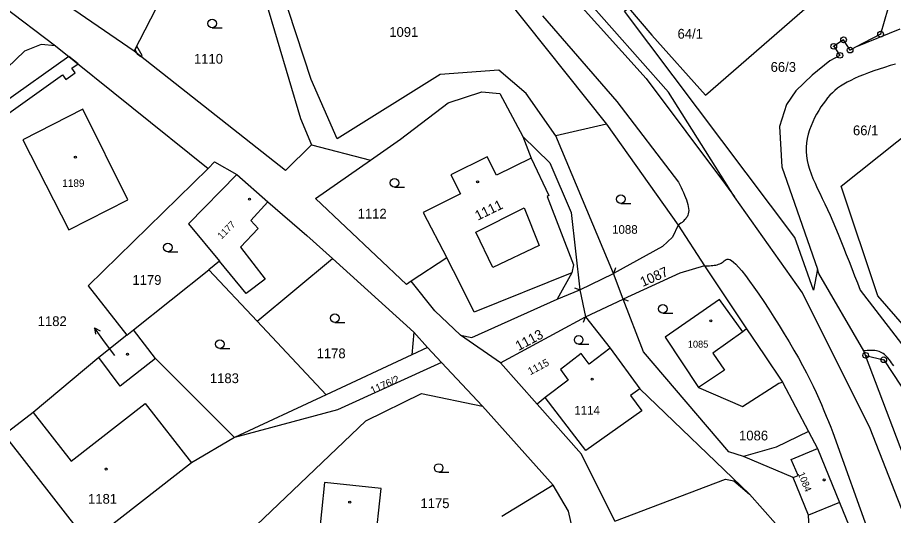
# Model space of a CAD drawing. Extents: x -504988 to -494607, y -1123820 to -1114018.
# Drawn here: x -497712.4 to -497559.8, y -1119487.8 to -1119400.9 of the extents above; entities that cross this region are included whole.
import ezdxf

# ---------------------------------------------------------------- set-up
doc = ezdxf.new("R2010")
doc.units = 0
for name, color, linetype in [('Hranice parcel', 7, 'Continuous'), ('Parcelní čísla', 7, 'Continuous'), ('Pop  PČ popisy', 7, 'Continuous'), ('Vnitřní kresba', 7, 'Continuous'), ('Věcná břemena k části', 7, 'Continuous'), ('Značky bodu BP', 7, 'Continuous'), ('Značky budov', 7, 'Continuous'), ('Značky kultur', 7, 'Continuous')]:
    doc.layers.add(name, color=color, linetype=linetype)

msp = doc.modelspace()

# ---------------------------------------------------------------- linework, layer by layer
at = {"layer": 'Hranice parcel'}
for p, q in [((-497640.86, -1119380.47), (-497609.75, -1119419.53)), ((-497692.07, -1119406.83), (-497682.53, -1119388.18)), ((-497692.07, -1119406.83), (-497711.51, -1119393.46)), ((-497715.1, -1119398.79), (-497705.77, -1119405.86)), ((-497705.77, -1119405.86), (-497679.17, -1119427.27)), ((-497609.75, -1119419.53), (-497618.56, -1119421.58)), ((-497609.75, -1119419.53), (-497597.28, -1119437.17)), ((-497608.52, -1119445.56), (-497618.56, -1119421.58)), ((-497661.14, -1119423.16), (-497650.9, -1119425.81)), ((-497597.28, -1119437.17), (-497592.68, -1119444.27)), ((-497670.65, -1119453.9), (-497657.53, -1119442.97)), ((-497692.2, -1119455.41), (-497679.07, -1119444.93)), ((-497679.07, -1119444.93), (-497670.65, -1119453.9)), ((-497606.86, -1119450.08), (-497608.52, -1119445.56)), ((-497592.68, -1119444.27), (-497585.34, -1119455.21)), ((-497614.4, -1119448.4), (-497613.4, -1119453.14)), ((-497628.22, -1119461.15), (-497613.4, -1119453.14)), ((-497613.4, -1119453.14), (-497609.12, -1119458.59)), ((-497670.65, -1119453.9), (-497658.59, -1119466.73)), ((-497693.35, -1119456.35), (-497692.2, -1119455.41)), ((-497688.32, -1119460.41), (-497692.2, -1119455.41)), ((-497628.22, -1119461.15), (-497635.18, -1119456.31)), ((-497693.35, -1119456.35), (-497698.21, -1119460.22)), ((-497638.51, -1119461.11), (-497640.96, -1119458.51)), ((-497564.6, -1119459.85), (-497564.89, -1119459.08)), ((-497674.56, -1119474.16), (-497688.32, -1119460.41)), ((-497550.62, -1119497.04), (-497564.6, -1119459.85)), ((-497631.38, -1119468.7), (-497638.51, -1119461.11)), ((-497621.82, -1119468.39), (-497628.22, -1119461.15)), ((-497579.08, -1119464.53), (-497574.57, -1119473.11)), ((-497658.59, -1119466.73), (-497674.56, -1119474.16)), ((-497631.38, -1119468.7), (-497619.07, -1119482.47)), ((-497714.71, -1119473.71), (-497700, -1119492.59)), ((-497619.07, -1119482.47), (-497627.97, -1119487.92))]:
    msp.add_line(p, q, dxfattribs=at)
for points in [[(-497682.53, -1119388.18), (-497678.13, -1119389.24), (-497673.06, -1119392.46), (-497669.18, -1119397.97), (-497663.1, -1119418.57), (-497661.14, -1119423.16)], [(-497618.56, -1119421.58), (-497623.74, -1119414.22), (-497628.54, -1119410.1), (-497638.72, -1119410.91), (-497656.7, -1119422.11), (-497661.2, -1119411.73), (-497667.82, -1119391.52)], [(-497605.92, -1119399.25), (-497601.85, -1119404.03), (-497592.53, -1119414.5), (-497565.47, -1119390.86)], [(-497565.47, -1119390.86), (-497560.73, -1119399.46), (-497561.99, -1119403.85), (-497566.37, -1119406.14), (-497567.32, -1119406.63), (-497568.45, -1119404.84), (-497570.16, -1119405.97), (-497569.1, -1119407.54), (-497570.84, -1119408.48), (-497573.91, -1119410.97), (-497576.78, -1119413.73), (-497578.4, -1119416.13), (-497579.64, -1119419.92), (-497579.2, -1119426.96), (-497573.02, -1119444.83)], [(-497534.22, -1119818.76), (-497527.7, -1119797.51), (-497526.57, -1119794.64), (-497519.56, -1119770.79), (-497516.99, -1119756.52), (-497516.74, -1119750.54), (-497517.29, -1119646.04), (-497517.49, -1119635.34), (-497517.68, -1119614.14), (-497518.78, -1119606.17), (-497521.17, -1119596.67), (-497524.36, -1119587.14), (-497528.66, -1119575.06), (-497536.08, -1119553.14), (-497545.22, -1119526.23), (-497548.05, -1119512.85), (-497563.82, -1119472.59), (-497575.6, -1119448.97), (-497587.45, -1119432.22), (-497598.97, -1119413.96), (-497613.75, -1119397.19), (-497616.09, -1119394)], [(-497573.02, -1119444.83), (-497573.67, -1119448.5), (-497576.94, -1119439.33), (-497606.6, -1119399.85), (-497605.92, -1119399.25)], [(-497705.77, -1119405.86), (-497708.27, -1119405.63), (-497711.19, -1119406.83), (-497760.1, -1119453.82), (-497752.95, -1119458.24), (-497750.43, -1119465.73)], [(-497661.14, -1119423.16), (-497665.72, -1119427.6), (-497692.07, -1119406.83)], [(-497650.9, -1119425.81), (-497645.65, -1119422.13), (-497637.35, -1119415.83), (-497631.5, -1119413.89), (-497628.34, -1119414.17), (-497624.36, -1119421.69)], [(-497552.64, -1119460.76), (-497562.49, -1119449.45), (-497568.85, -1119430.36), (-497549.48, -1119414.92)], [(-497693.16, -1119432.73), (-497701.01, -1119416.95), (-497711.46, -1119422.26), (-497703.47, -1119437.95), (-497693.16, -1119432.73)], [(-497624.36, -1119421.69), (-497622.89, -1119425.48), (-497628.93, -1119428.44), (-497630.55, -1119425.22), (-497636.86, -1119428.4), (-497635.21, -1119431.69), (-497641.72, -1119434.94), (-497637.61, -1119442.83), (-497643.77, -1119446.92)], [(-497624.36, -1119421.69), (-497619.61, -1119426.29), (-497615.91, -1119434.92), (-497614.4, -1119448.4)], [(-497643.77, -1119446.92), (-497644.6, -1119447.47), (-497660.47, -1119432.53), (-497650.9, -1119425.81)], [(-497679.17, -1119427.27), (-497700.07, -1119447.75), (-497693.35, -1119456.35)], [(-497679.17, -1119427.27), (-497678.07, -1119426.12), (-497674.15, -1119428.32)], [(-497674.15, -1119428.32), (-497682.61, -1119436.91), (-497677.19, -1119443.44), (-497679.07, -1119444.93)], [(-497674.15, -1119428.32), (-497668.75, -1119433.1), (-497661.96, -1119438.95), (-497657.53, -1119442.97)], [(-497597.28, -1119437.17), (-497598.23, -1119439.27), (-497600.01, -1119440.86), (-497608.52, -1119445.56)], [(-497657.53, -1119442.97), (-497643.34, -1119455.83), (-497640.96, -1119458.51)], [(-497592.68, -1119444.27), (-497596.99, -1119445.5), (-497606.86, -1119450.08)], [(-497564.89, -1119459.08), (-497572.75, -1119445.6), (-497573.02, -1119444.83)], [(-497635.18, -1119456.31), (-497639.67, -1119452.11), (-497643.77, -1119446.92)], [(-497635.18, -1119456.31), (-497633.25, -1119456.73), (-497618.35, -1119450.04), (-497614.4, -1119448.4)], [(-497585.9, -1119477.5), (-497588.42, -1119476.65), (-497603.33, -1119459.22), (-497606.86, -1119450.08)], [(-497585.34, -1119455.21), (-497586.01, -1119455.76), (-497590.07, -1119450.09), (-497599.56, -1119456.68), (-497593.72, -1119465.46), (-497586.09, -1119468.78), (-497579.72, -1119464.7), (-497579.08, -1119464.53)], [(-497585.34, -1119455.21), (-497582.3, -1119459.75), (-497579.08, -1119464.53)], [(-497640.96, -1119458.51), (-497643.66, -1119459.77), (-497658.59, -1119466.73)], [(-497609.12, -1119458.59), (-497612.76, -1119461.36), (-497614.15, -1119459.53), (-497617.8, -1119462.34), (-497616.43, -1119464.15), (-497620.43, -1119467.2), (-497621.82, -1119468.39)], [(-497609.12, -1119458.59), (-497603.95, -1119465.69), (-497584.82, -1119484.08)], [(-497698.21, -1119460.22), (-497709.69, -1119469.8), (-497714.71, -1119473.71)], [(-497688.32, -1119460.41), (-497694.5, -1119465.25), (-497698.21, -1119460.22)], [(-497564.6, -1119459.85), (-497561.45, -1119460.61), (-497553.96, -1119472.01), (-497537.91, -1119494.15)], [(-497638.51, -1119461.11), (-497656.63, -1119469.34), (-497674.56, -1119474.16)], [(-497670.72, -1119489.47), (-497651.69, -1119471.25), (-497642.02, -1119466.49), (-497631.38, -1119468.7)], [(-497608.32, -1119488.74), (-497614.14, -1119477.09), (-497621.82, -1119468.39)], [(-497574.57, -1119473.11), (-497580.2, -1119475.88), (-497585.9, -1119477.5)], [(-497574.57, -1119473.11), (-497572.99, -1119476.08), (-497569.18, -1119485.53), (-497566.97, -1119490.89)], [(-497674.56, -1119474.16), (-497682.06, -1119478.61), (-497700, -1119492.59)], [(-497574.28, -1119493.19), (-497574.58, -1119487.69), (-497577.21, -1119481.15), (-497585.9, -1119477.5)], [(-497655.54, -1119502.25), (-497650.53, -1119499.37), (-497650.13, -1119493.31), (-497649.04, -1119483.09), (-497658.87, -1119482.04), (-497659.96, -1119492.25), (-497658.33, -1119497.4), (-497655.54, -1119502.25)], [(-497608.32, -1119488.74), (-497589, -1119481.44), (-497587.57, -1119481.74), (-497584.82, -1119484.08)], [(-497608.1, -1119523.83), (-497616.4, -1119487.03), (-497619.07, -1119482.47)], [(-497584.82, -1119484.08), (-497580.33, -1119489.19), (-497578.59, -1119497.9), (-497580.72, -1119500.24)]]:
    msp.add_lwpolyline(points, dxfattribs=at)
at = {"layer": 'Pop  PČ popisy'}
for p, q in [((-497697.21, -1119457.47), (-497698.97, -1119455.04)), ((-497698.97, -1119455.04), (-497697.98, -1119455.56)), ((-497698.97, -1119455.04), (-497698.79, -1119456.15)), ((-497695.45, -1119459.9), (-497697.21, -1119457.47))]:
    msp.add_line(p, q, dxfattribs=at)
at = {"layer": 'Vnitřní kresba'}
for p, q in [((-497615.86, -1119397.09), (-497602.87, -1119411.56)), ((-497620.89, -1119400.65), (-497607.94, -1119415.57)), ((-497558.65, -1119403), (-497566.37, -1119406.14)), ((-497602.87, -1119411.56), (-497589.05, -1119430.07)), ((-497607.94, -1119415.57), (-497597.22, -1119429.65)), ((-497622.89, -1119425.48), (-497619.81, -1119431.99)), ((-497589.05, -1119430.07), (-497587.45, -1119432.22)), ((-497668.75, -1119433.1), (-497671.71, -1119436.35)), ((-497619.81, -1119431.99), (-497620.12, -1119432.14)), ((-497620.12, -1119432.14), (-497615.51, -1119444.08)), ((-497632.53, -1119438.36), (-497624.11, -1119434.14)), ((-497624.11, -1119434.14), (-497621.49, -1119440.7)), ((-497671.71, -1119436.35), (-497670.48, -1119437.74)), ((-497670.48, -1119437.74), (-497673.51, -1119441)), ((-497629.55, -1119444.56), (-497632.53, -1119438.36)), ((-497673.51, -1119441), (-497669.26, -1119446.59)), ((-497621.49, -1119440.7), (-497629.55, -1119444.56)), ((-497672.53, -1119449.06), (-497677.19, -1119443.44)), ((-497635.24, -1119447.37), (-497637.61, -1119442.83)), ((-497615.51, -1119444.08), (-497615.82, -1119445.46)), ((-497615.82, -1119445.46), (-497632.81, -1119452.3)), ((-497615.82, -1119445.46), (-497618.35, -1119450.04)), ((-497614.4, -1119448.4), (-497608.52, -1119445.56)), ((-497608.19, -1119444.61), (-497608.52, -1119445.56)), ((-497669.26, -1119446.59), (-497672.53, -1119449.06)), ((-497632.81, -1119452.3), (-497635.24, -1119447.37)), ((-497615.35, -1119448.07), (-497614.4, -1119448.4)), ((-497565.57, -1119448.47), (-497555.15, -1119462.06)), ((-497613.4, -1119453.14), (-497606.86, -1119450.08)), ((-497605.92, -1119450.42), (-497606.86, -1119450.08)), ((-497613.74, -1119454.08), (-497613.4, -1119453.14)), ((-497643.34, -1119455.83), (-497643.66, -1119459.77)), ((-497586.01, -1119455.76), (-497591.21, -1119459.47)), ((-497591.21, -1119459.47), (-497589.17, -1119462.43)), ((-497589.17, -1119462.43), (-497593.72, -1119465.46)), ((-497603.95, -1119465.69), (-497605.55, -1119466.85)), ((-497605.55, -1119466.85), (-497603.59, -1119469.55)), ((-497703.05, -1119478.32), (-497690.13, -1119468.25)), ((-497690.13, -1119468.25), (-497682.06, -1119478.61)), ((-497613.38, -1119476.45), (-497620.43, -1119467.2)), ((-497709.69, -1119469.8), (-497703.05, -1119478.32)), ((-497603.59, -1119469.55), (-497613.38, -1119476.45)), ((-497570.31, -1119473.32), (-497559.84, -1119502.49)), ((-497577.57, -1119478.03), (-497572.99, -1119476.08)), ((-497576.39, -1119480.8), (-497577.57, -1119478.03)), ((-497577.21, -1119481.15), (-497576.39, -1119480.8)), ((-497569.18, -1119485.53), (-497574.58, -1119487.69))]:
    msp.add_line(p, q, dxfattribs=at)
for points in [[(-497559.4, -1119409.06), (-497560.34, -1119409.34), (-497561.29, -1119409.64), (-497562.25, -1119409.96), (-497563.18, -1119410.27), (-497564.09, -1119410.59), (-497564.96, -1119410.92), (-497565.77, -1119411.25), (-497566.52, -1119411.57), (-497567.21, -1119411.9), (-497567.85, -1119412.23), (-497568.43, -1119412.57), (-497568.98, -1119412.93), (-497569.48, -1119413.29), (-497569.95, -1119413.67), (-497570.4, -1119414.08), (-497570.82, -1119414.51), (-497571.23, -1119414.96), (-497571.62, -1119415.46), (-497572.01, -1119415.98), (-497572.4, -1119416.54), (-497572.78, -1119417.14), (-497573.15, -1119417.77), (-497573.49, -1119418.43), (-497573.83, -1119419.12), (-497574.12, -1119419.82), (-497574.39, -1119420.54), (-497574.61, -1119421.28), (-497574.79, -1119422.03), (-497574.92, -1119422.79), (-497574.98, -1119423.56), (-497574.99, -1119424.32), (-497574.93, -1119425.08), (-497574.8, -1119425.85), (-497574.62, -1119426.62), (-497574.39, -1119427.4), (-497574.1, -1119428.2), (-497573.78, -1119429.01), (-497573.42, -1119429.83), (-497573.03, -1119430.69), (-497572.61, -1119431.57), (-497572.18, -1119432.48), (-497571.73, -1119433.43), (-497571.27, -1119434.41), (-497570.81, -1119435.43), (-497570.34, -1119436.5), (-497569.87, -1119437.6), (-497569.4, -1119438.72), (-497568.92, -1119439.89), (-497568.45, -1119441.06), (-497567.98, -1119442.26), (-497567.49, -1119443.49), (-497567.01, -1119444.72), (-497566.54, -1119445.96), (-497566.05, -1119447.22), (-497565.57, -1119448.47)], [(-497597.22, -1119429.65), (-497597, -1119430.11), (-497596.77, -1119430.57), (-497596.56, -1119431.02), (-497596.35, -1119431.47), (-497596.16, -1119431.91), (-497595.98, -1119432.34), (-497595.83, -1119432.76), (-497595.69, -1119433.16), (-497595.58, -1119433.55), (-497595.5, -1119433.92), (-497595.45, -1119434.27), (-497595.43, -1119434.59), (-497595.45, -1119434.89), (-497595.51, -1119435.17), (-497595.59, -1119435.43), (-497595.71, -1119435.67), (-497595.85, -1119435.89), (-497596.01, -1119436.1), (-497596.2, -1119436.3), (-497596.4, -1119436.49), (-497596.6, -1119436.66), (-497596.82, -1119436.83), (-497597.05, -1119437), (-497597.28, -1119437.17)], [(-497592.68, -1119444.27), (-497592.39, -1119444.26), (-497592.1, -1119444.25), (-497591.81, -1119444.23), (-497591.53, -1119444.21), (-497591.25, -1119444.18), (-497590.98, -1119444.15), (-497590.72, -1119444.1), (-497590.47, -1119444.04), (-497590.23, -1119443.98), (-497590.01, -1119443.89), (-497589.8, -1119443.79), (-497589.61, -1119443.67), (-497589.43, -1119443.53), (-497589.27, -1119443.39), (-497589.1, -1119443.27), (-497588.93, -1119443.16), (-497588.74, -1119443.1), (-497588.52, -1119443.1), (-497588.27, -1119443.16), (-497587.98, -1119443.32), (-497587.63, -1119443.58), (-497587.23, -1119443.95), (-497586.74, -1119444.46), (-497586.19, -1119445.12), (-497585.55, -1119445.93), (-497584.83, -1119446.9), (-497584.06, -1119447.99), (-497583.23, -1119449.17), (-497582.36, -1119450.47), (-497581.48, -1119451.81), (-497580.58, -1119453.21), (-497579.67, -1119454.65), (-497578.78, -1119456.09), (-497577.92, -1119457.52), (-497577.09, -1119458.95), (-497576.31, -1119460.31), (-497575.59, -1119461.61), (-497574.93, -1119462.87), (-497574.32, -1119464.06), (-497573.76, -1119465.21), (-497573.23, -1119466.32), (-497572.75, -1119467.39), (-497572.3, -1119468.42), (-497571.87, -1119469.44), (-497571.46, -1119470.43), (-497571.07, -1119471.4), (-497570.68, -1119472.37), (-497570.31, -1119473.32)], [(-497559.71, -1119461.69), (-497559.9, -1119461.41), (-497560.09, -1119461.13), (-497560.28, -1119460.86), (-497560.48, -1119460.6), (-497560.68, -1119460.36), (-497560.89, -1119460.13), (-497561.1, -1119459.92), (-497561.31, -1119459.73), (-497561.53, -1119459.55), (-497561.76, -1119459.41), (-497561.99, -1119459.29), (-497562.24, -1119459.19), (-497562.48, -1119459.12), (-497562.74, -1119459.07), (-497563, -1119459.03), (-497563.26, -1119459.01), (-497563.53, -1119459), (-497563.8, -1119459), (-497564.07, -1119459.01), (-497564.34, -1119459.03), (-497564.62, -1119459.05), (-497564.89, -1119459.08)]]:
    msp.add_lwpolyline(points, dxfattribs=at)
at = {"layer": 'Věcná břemena k části'}
for points in [[(-497691.93, -1119406.55), (-497691.52, -1119407.27), (-497690.93, -1119407.73), (-497690.65, -1119407.57), (-497691.6, -1119405.92)], [(-497753.92, -1119441.18), (-497751.99, -1119441.47), (-497747.11, -1119442.19), (-497750.53, -1119447.61), (-497748.84, -1119448.68), (-497744.68, -1119442.09), (-497725.6, -1119426.06), (-497720.57, -1119439.03), (-497718.71, -1119438.3), (-497723.96, -1119424.76), (-497704.53, -1119410.93), (-497703.95, -1119411.75), (-497702.32, -1119410.59), (-497702.9, -1119409.77), (-497701.85, -1119409.02), (-497703.46, -1119407.72), (-497726.38, -1119424.04), (-497746.05, -1119440.32), (-497750.41, -1119439.68), (-497751.5, -1119439.52), (-497751.33, -1119438.73), (-497753.28, -1119438.3)]]:
    msp.add_lwpolyline(points, close=True, dxfattribs=at)
at = {"layer": 'Značky bodu BP'}
for centre, radius in [((-497568.45, -1119404.84), 0.5), ((-497561.99, -1119403.85), 0.5), ((-497561.99, -1119403.85), 0.0303), ((-497570.16, -1119405.97), 0.5), ((-497570.16, -1119405.97), 0.0303), ((-497568.45, -1119404.84), 0.0303), ((-497569.1, -1119407.54), 0.5), ((-497567.32, -1119406.63), 0.5), ((-497567.32, -1119406.63), 0.0303), ((-497569.1, -1119407.54), 0.0303), ((-497564.6, -1119459.85), 0.5), ((-497564.6, -1119459.85), 0.0303), ((-497561.45, -1119460.61), 0.5), ((-497561.45, -1119460.61), 0.0303)]:
    msp.add_circle(centre, radius, dxfattribs=at)
at = {"layer": 'Značky budov'}
for centre in [(-497702.31, -1119425.28), (-497632.21, -1119429.59), (-497671.96, -1119432.6), (-497591.56, -1119453.83), (-497693.21, -1119459.67), (-497612.25, -1119464), (-497696.94, -1119479.67), (-497571.82, -1119481.58), (-497654.51, -1119485.47)]:
    msp.add_circle(centre, 0.175, dxfattribs=at)
at = {"layer": 'Značky kultur'}
for p, q in [((-497678.47, -1119402.74), (-497676.72, -1119402.74)), ((-497646.69, -1119430.51), (-497644.94, -1119430.51)), ((-497607.25, -1119433.35), (-497605.5, -1119433.35)), ((-497686.21, -1119441.8), (-497684.46, -1119441.8)), ((-497599.96, -1119452.47), (-497598.21, -1119452.47)), ((-497657.08, -1119454.1), (-497655.33, -1119454.1)), ((-497677.15, -1119458.65), (-497675.4, -1119458.65)), ((-497614.61, -1119457.9), (-497612.86, -1119457.9)), ((-497639, -1119480.24), (-497637.25, -1119480.24))]:
    msp.add_line(p, q, dxfattribs=at)
for centre in [(-497678.47, -1119401.99), (-497646.69, -1119429.76), (-497607.25, -1119432.6), (-497686.21, -1119441.05), (-497599.96, -1119451.72), (-497657.08, -1119453.35), (-497677.15, -1119457.9), (-497614.61, -1119457.15), (-497639, -1119479.49)]:
    msp.add_circle(centre, 0.75, dxfattribs=at)

# ---------------------------------------------------------------- texts
at = {"layer": 'Parcelní čísla'}
for s, height, p in [('1091', 1.7, (-497647.61, -1119404.32)), ('64/1', 1.7, (-497597.38, -1119404.63)), ('1110', 1.7, (-497681.65, -1119408.99)), ('66/3', 1.7, (-497581.16, -1119410.42)), ('66/1', 1.7, (-497566.81, -1119421.47)), ('1189', 1.3, (-497704.59, -1119430.47)), ('1112', 1.7, (-497653.12, -1119435.99)), ('1088', 1.5, (-497608.79, -1119438.65)), ('1179', 1.7, (-497692.37, -1119447.56)), ('1182', 1.7, (-497708.87, -1119454.74)), ('1085', 1.2, (-497595.59, -1119458.5)), ('1178', 1.7, (-497660.27, -1119460.35)), ('1183', 1.7, (-497678.87, -1119464.69)), ('1114', 1.5, (-497615.37, -1119470.17)), ('1086', 1.7, (-497586.66, -1119474.68)), ('1181', 1.7, (-497700.1, -1119485.72)), ('1175', 1.7, (-497642.18, -1119486.49))]:
    msp.add_text(s, height=height, dxfattribs=at).set_placement(p)
for s, height, rotation, p in [('1111', 1.7, 26, (-497632.18, -1119436.38)), ('1177', 1.2, 45, (-497676.84, -1119439.68)), ('1087', 1.7, 24, (-497603.44, -1119447.94)), ('1113', 1.7, 28, (-497625.07, -1119459.1)), ('1115', 1.3, 28, (-497623.03, -1119463.33)), ('1176/2', 1.3, 24, (-497650.55, -1119466.63)), ('1084', 1.2, 292, (-497576.43, -1119480.47))]:
    msp.add_text(s, height=height, rotation=rotation, dxfattribs=at).set_placement(p)

doc.saveas('drawing.dxf')
